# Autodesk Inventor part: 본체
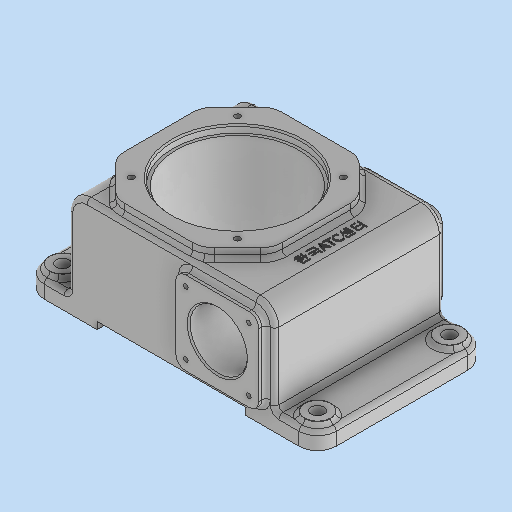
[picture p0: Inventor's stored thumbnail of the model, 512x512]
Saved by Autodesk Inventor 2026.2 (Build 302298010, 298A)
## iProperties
Created: 2026-02
Part Number: 본체
Material: 일반
Document SubType Name: Modeling
Designer: PC2-14
Density: 1 g/cm^3
Appearance: 기본값
Author: PC2-14
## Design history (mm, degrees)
sketch "스케치1"
  geometry: L1 (-102, 59)-(102, 59); L2 (102, 59)-(102, -59); L3 (102, -59)-(-102, -59); L4 (-102, -59)-(-102, 59); 3 further points
  constraints: 8 end point, 2 midpoint, 2 parallel, 1 horizontal, 1 horizontal alignment, 1 perpendicular, 1 vertical alignment
  dimensions: "d0" = 204 distance between parallel lines of L2 L4; "d1" = 118 distance between parallel lines of L3 L1
extrude "돌출1" new body sketch "스케치1" distance "d2" = 75; taper "d3" = 0 deg
sketch "스케치2"
  geometry: L1 (0, 0)-(204, 0) reference; L2 (50, 0)-(154, 0); L3 (154, 0)-(154, 5); L4 (154, 5)-(50, 5); L5 (50, 5)-(50, 0); 3 further points
  constraints: 8 end point, 2 parallel, 1 horizontal, 1 midpoint, 1 perpendicular, 1 point on line
  dimensions: "d4" = 52 distance from line of point (102, 0) L5; "d5" = 104 distance between parallel lines of L3 L5; "d6" = 5 distance between parallel lines of L1 L4
extrude "돌출2" cut sketch "스케치2" extent not by distance; stored distance "d7" = 75; taper "d8" = 0 deg
sketch "스케치3"
  geometry: L1 (-102, 59)-(-102, -59) reference; L2 (-102, 59)-(-72, 59); L3 (-72, 59)-(-72, -59); L4 (-72, -59)-(-102, -59); L5 (-102, -59)-(-102, 59); L6 (102, 59)-(52, 59) reference; L7 (52, -59)-(102, -59) reference; L8 (72, 59)-(102, 59); L9 (102, 59)-(102, -59); L10 (102, -59)-(72, -59); L11 (72, -59)-(72, 59); 3 further points
  constraints: 16 end point, 4 parallel, 2 horizontal, 2 perpendicular, 2 point on line
  dimensions: "d9" = 30 distance between parallel lines of L3 L1; "d10" = 30 distance between parallel lines of L9 L11
extrude "돌출3" cut sketch "스케치3" distance "d11" = 63; taper "d12" = 0 deg
sketch "스케치5"
  geometry: L1 (72, 59)-(-72, 59) reference; L2 (-102, -59)-(-102, 59) reference; C1 r 9 at (-89, 46); C2 r 9 at (-89, -46); C3 r 9 at (89, 46); C4 r 9 at (89, -46); 3 further points
  constraints: 4 centre point, 2 equal radius, 2 horizontal alignment, 2 midpoint, 2 vertical alignment
  dimensions: "d16" = 18 diameter of C1; "d17" = 18 diameter of C3; "d18" = 178 distance of C3.centre C1.centre; "d19" = 89 horizontal distance of point (0, 59) C1.centre; "d21" = 46 vertical distance of point (-102, 0) C2.centre; "d22" = 92 distance of C1.centre C2.centre
extrude "돌출4" join sketch "스케치5" distance "d23" = 3; taper "d24" = 0 deg
sketch "스케치6"
  geometry: L1 (110, 69)-(168, 69); L2 (168, 69)-(168, 11); L3 (168, 11)-(110, 11); L4 (110, 11)-(110, 69); L5 (154, 0)-(204, 0) reference; L6 (200, 15)-(182, 15) reference; 4 further points
  constraints: 8 end point, 3 midpoint, 2 parallel, 1 horizontal, 1 perpendicular
  dimensions: "d25" = 58 distance between parallel lines of L2 L4; "d26" = 58 distance between parallel lines of L1 L3; "d27" = 40 distance from line of L5 point (168, 40); "d28" = 52 horizontal distance of point (139, 11) point (191, 15)
extrude "돌출5" join sketch "스케치6" distance "d29" = 5; taper "d30" = 0 deg
sketch "스케치7"
  geometry: L1 (-43, -55)-(17, -55); L2 (42, -30)-(42, 30); L3 (17, 55)-(-43, 55); L4 (-68, 30)-(-68, -30); L5 (-68, -55)-(42, 55); L6 (42, -55)-(-68, 55); L7 (-43, -55)-(-68, -30); L8 (-68, 30)-(-43, 55); L9 (42, 30)-(17, 55); L10 (42, -30)-(17, -55); L11 (102, 59)-(102, -59) reference; 2 further points
  constraints: 20 end point, 8 point on line, 3 midpoint, 2 parallel, 1 horizontal, 1 horizontal alignment, 1 perpendicular
  dimensions: "d42" = 110 distance between parallel lines of L2 L4; "d43" = 110 distance between parallel lines of L3 L1; "d44" = 25 distance of L1.start L5.start; "d45" = 25 distance of L4.end L5.start (= d44); "d46" = 25 distance of L4.start L6.end (= d44); "d47" = 25 distance of L3.end L6.end (= d46); "d48" = 25 distance of L2.end L5.end (= d44); "d49" = 25 distance of L3.start L5.end (= d48); "d50" = 25 distance of L2.start L6.start (= d44); "d51" = 25 distance of L1.end L6.start (= d50); "d52" = 115 distance from line of point (-13, 0) L11
extrude "돌출6" join sketch "스케치7" distance "d53" = 7; taper "d54" = 0 deg
fillet "모깎기1" dims "d55" = 13
sketch "스케치8"
  geometry: L1 (43, 82)-(-17, 82) reference; L2 (13, 82)-(13, 77); L3 (13, 77)-(58, 77); L4 (58, 77)-(58, 82); L5 (58, 82)-(13, 82); 2 further points
  constraints: 8 end point, 2 perpendicular, 1 collinear, 1 midpoint, 1 vertical
  dimensions: "d56" = 5 distance between parallel lines of L3 L1; "d57" = 90 diameter of L4 L2
revolve "회전1" sketch "스케치8" stored, may be unused: angle "d58" = 90 deg
chamfer "모따기1" distance "d59" = 1; stored, may be unused: second distance "d60" = 2, angle "d61" = 45 deg
sketch "스케치9"
  geometry: L1 (58, 77)-(-32, 77) reference; L2 (13, 77)-(13, 22); L3 (13, 22)-(36.757, 22); L4 (38.879, 21.121)-(43.121, 16.879); L5 (45.243, 16)-(56, 16); L6 (56, 16)-(56, 77); L7 (13, 77)-(56, 77); L8 (-17, 75)-(43, 75) reference; A1 r 3 centre (36.757, 19) between (38.879, 21.121) and (36.757, 22); A2 r 3 centre (45.243, 19) between (43.121, 16.879) and (45.243, 16); 3 further points
  constraints: 12 end point, 5 point on line, 4 point on circle, 4 tangent, 2 centre point, 2 parallel, 2 perpendicular, 1 midpoint, 1 vertical
  dimensions: "d62" = 61 distance between parallel lines of L5 L1; "d63" = 86 diameter of L6 L2; "d64" = 45 deg angle of L2 L4; "d65" = 50 diameter of point (38, 22) L2; "d66" = 6 distance between parallel lines of L5 L3; "d76" = 3 radius of A1 (derived); "d77" = 3 radius of A2 (derived)
revolve "회전2" sketch "스케치9" stored, may be unused: angle "d67" = 90 deg
fillet "모깎기3" dims "d75" = 3
sketch "스케치11"
  geometry: L1 (36.757, 22)-(-10.757, 22) reference; L2 (13, 22)-(13, 11); L3 (13, 11)-(33, 11); L4 (33, 11)-(33, 22); L5 (13, 22)-(33, 22); 1 further point
  constraints: 8 end point, 3 perpendicular, 1 midpoint, 1 point on line, 1 vertical
  dimensions: "d78" = 11 distance between parallel lines of L3 L1; "d79" = 40 diameter of L4 L2
revolve "회전4" sketch "스케치11" stored, may be unused: angle "d80" = 90 deg
chamfer "모따기3" distance "d81" = 1; stored, may be unused: second distance "d82" = 2, angle "d83" = 45 deg
fillet "모깎기4" dims "d84" = 1.5
sketch "스케치12"
  geometry: L1 (168, 11)-(168, 69) reference; L2 (168, 69)-(110, 69) reference; C1 r 20 at (139, 40); 3 further points
  constraints: 2 midpoint, 1 centre point, 1 horizontal alignment, 1 vertical alignment
  dimensions: "d85" = 40 diameter of C1
extrude "돌출7" cut sketch "스케치12" extent not by distance; stored distance "d86" = 0; taper "d87" = 0 deg
sketch "스케치13"
  geometry: C1 r 18.5 at (-13, 0) reference; 5 further points
  constraints: 2 horizontal alignment, 2 vertical alignment
  dimensions: "d88" = 74 distance of point (24, 37) point (-50, 37); "d89" = 74 distance of point (-50, -37) point (-50, 37); "d90" = 37 vertical distance of point (0, 0) point (-50, 37); "d91" = 37 horizontal distance of C1.centre point (24, 37)
hole "구멍1" sketch "스케치13" at (-50, 37), (-50, -37), (24, -37), (24, 37) diameter "d92" = 4.134; stored, may be unused: countersink angle "d96" = 90 deg, drill point angle "d98" = 118 deg; dims "d93" = 10, "d94" = 4, "d95" = 2, "d97" = 12
sketch "스케치14"
  geometry: L1 (110, 69)-(110, 11) reference; L2 (168, 69)-(110, 69) reference; 7 further points
  constraints: 2 horizontal alignment, 2 midpoint, 2 vertical alignment
  dimensions: "d99" = 44 distance of point (161, 62) point (117, 62); "d100" = 44 distance of point (117, 18) point (117, 62); "d101" = 22 vertical distance of point (110, 40) point (117, 62); "d102" = 22 horizontal distance of point (139, 69) point (117, 62)
hole "구멍2" sketch "스케치14" at (117, 62), (161, 62), (117, 18), (161, 18) diameter "d103" = 3.242; stored, may be unused: countersink angle "d107" = 90 deg, drill point angle "d109" = 118 deg; dims "d104" = 8, "d105" = 4, "d106" = 2, "d108" = 10
chamfer "모따기4" distance "d110" = 1; stored, may be unused: second distance "d111" = 2, angle "d112" = 45 deg
chamfer "모따기5" distance "d113" = 1; stored, may be unused: second distance "d114" = 2, angle "d115" = 45 deg
sketch "스케치15"
  geometry: C1 r 9 at (0, 0) reference; C2 r 9 at (0, 92) reference; C3 r 9 at (-178, 0) reference; C4 r 9 at (-178, 92) reference; 5 further points
  constraints: 4 coincident
hole "구멍3" sketch "스케치15" at (0, 0), (0, 92), (-178, 0), (-178, 92) diameter "d116" = 9; stored, may be unused: countersink angle "d120" = 90 deg, drill point angle "d122" = 118 deg; dims "d117" = 8, "d118" = 4, "d119" = 2, "d121" = 10
fillet "모깎기5" dims "d123" = 13
fillet "모깎기6" dims "d124" = 7
fillet "모깎기7" dims "d125" = 3
fillet "모깎기8" dims "d126" = 3
fillet "모깎기9" dims "d127" = 3
fillet "모깎기10" dims "d128" = 15
fillet "모깎기11" dims "d129" = 3
fillet "모깎기12" dims "d130" = 2.9
sketch "스케치16"
  geometry: L1 (48.623, -23.864)-(48.623, 23.864); L2 (48.623, 23.864)-(55.377, 23.864); L3 (55.377, 23.864)-(55.377, -23.864); L4 (55.377, -23.864)-(48.623, -23.864); C1 r 18.5 at (-13, 0) reference; 3 further points
  constraints: 2 midpoint, 1 horizontal alignment, 2 other
  dimensions: "d131" = 65 horizontal distance of point (52, -23.864) C1.centre
feature "엠보싱1" sketch "스케치16" dims "d132" = 0.5, "d133" = 0
node "솔리드1"
mirror "미러1"
mirror "미러2"
feature "A9D066F2-1C7D-4E18-AEED-F7BC21143FA4" dims "d116" = 9, "d117" = 8, "d118" = 4, "d119" = 2, "d120" = 90 deg, "d121" = 10, "d122" = 118 deg
